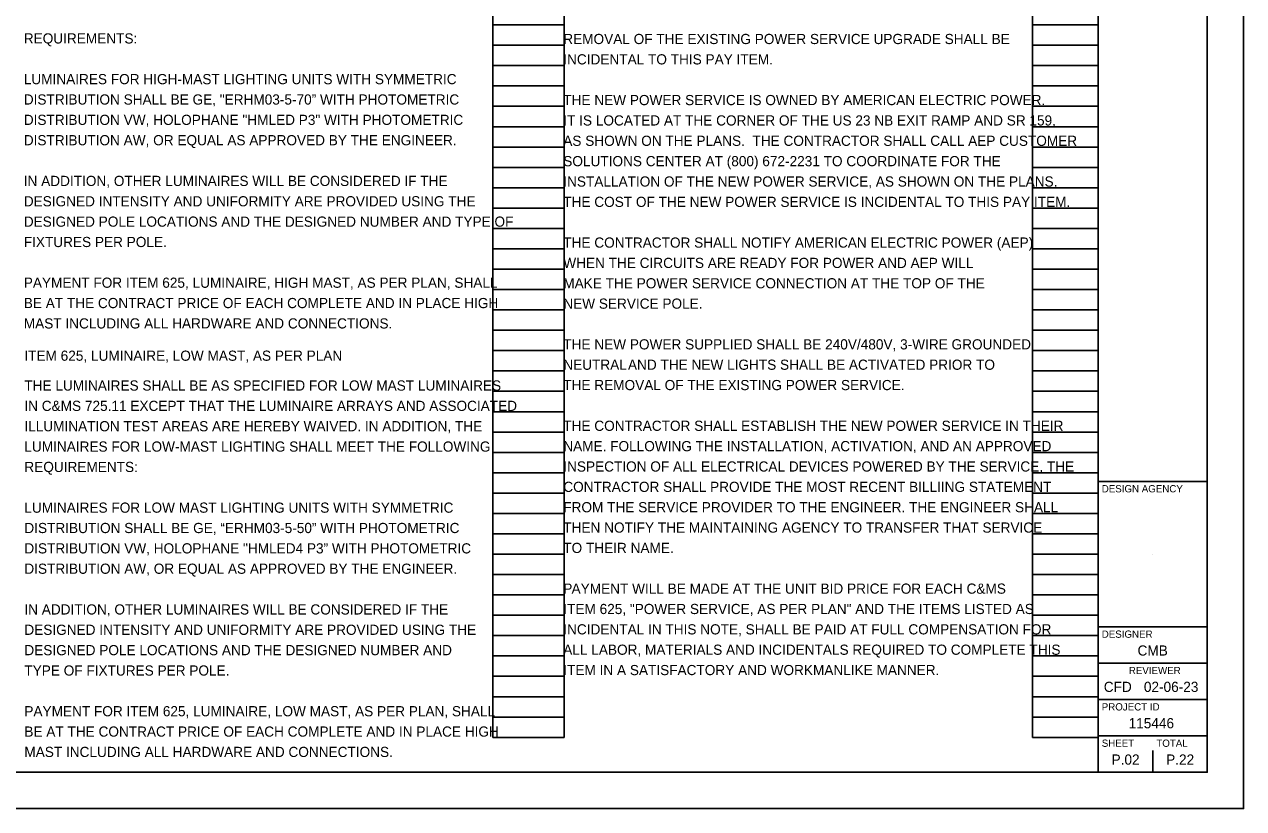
# Model space of a CAD drawing. Extents: x 0 to 34, y 0 to 22.
# Drawn here: x 17.24 to 34, y 0 to 10.79 of the extents above; entities that cross this region are included whole.
import ezdxf

# ---------------------------------------------------------------- set-up
doc = ezdxf.new("R2010")
doc.units = 0
for name, color, linetype in [('Default', 7, 'Continuous'), ('SH_Border', 7, 'Continuous'), ('SH_Cut_Line', 7, 'Continuous'), ('SH_Data', 7, 'Continuous'), ('SH_Text', 7, 'Continuous')]:
    doc.layers.add(name, color=color, linetype=linetype)

msp = doc.modelspace()

# ---------------------------------------------------------------- linework, layer by layer
at = {"layer": 'SH_Border'}
for p, q in [((32, 0.5), (32, 21.5)), ((32, 4.5), (33.5, 4.5)), ((32, 2.5), (33.5, 2.5)), ((32, 2), (33.5, 2)), ((32, 1.5), (33.5, 1.5)), ((32, 1), (33.5, 1))]:
    msp.add_line(p, q, dxfattribs=at)
msp.add_lwpolyline([(1.5, 21.5), (33.5, 21.5), (33.5, 0.5), (1.5, 0.5)], close=True, dxfattribs=at)
at = {"layer": 'SH_Cut_Line'}
msp.add_lwpolyline([(0, 0), (34, 0), (34, 22), (0, 22)], close=True, dxfattribs=at)
at = {"layer": 'SH_Data'}
for p, q in [((23.68, 0.98), (23.68, 21.14)), ((24.66, 0.98), (24.66, 21.14)), ((31.1, 0.98), (31.1, 21.14)), ((32, 0.98), (32, 21.14)), ((23.68, 10.78), (24.66, 10.78)), ((31.1, 10.78), (32, 10.78)), ((23.68, 10.5), (24.66, 10.5)), ((31.1, 10.5), (32, 10.5)), ((23.68, 10.22), (24.66, 10.22)), ((31.1, 10.22), (32, 10.22)), ((23.68, 9.94), (24.66, 9.94)), ((31.1, 9.94), (32, 9.94)), ((23.68, 9.66), (24.66, 9.66)), ((31.1, 9.66), (32, 9.66)), ((23.68, 9.38), (24.66, 9.38)), ((31.1, 9.38), (32, 9.38)), ((23.68, 9.1), (24.66, 9.1)), ((31.1, 9.1), (32, 9.1)), ((23.68, 8.82), (24.66, 8.82)), ((31.1, 8.82), (32, 8.82)), ((23.68, 8.54), (24.66, 8.54)), ((31.1, 8.54), (32, 8.54)), ((23.68, 8.26), (24.66, 8.26)), ((31.1, 8.26), (32, 8.26)), ((23.68, 7.98), (24.66, 7.98)), ((31.1, 7.98), (32, 7.98)), ((23.68, 7.7), (24.66, 7.7)), ((31.1, 7.7), (32, 7.7)), ((23.68, 7.42), (24.66, 7.42)), ((31.1, 7.42), (32, 7.42)), ((23.68, 7.14), (24.66, 7.14)), ((31.1, 7.14), (32, 7.14)), ((23.68, 6.86), (24.66, 6.86)), ((31.1, 6.86), (32, 6.86)), ((23.68, 6.58), (24.66, 6.58)), ((31.1, 6.58), (32, 6.58)), ((23.68, 6.3), (24.66, 6.3)), ((31.1, 6.3), (32, 6.3)), ((23.68, 6.02), (24.66, 6.02)), ((31.1, 6.02), (32, 6.02)), ((23.68, 5.74), (24.66, 5.74)), ((31.1, 5.74), (32, 5.74)), ((23.68, 5.46), (24.66, 5.46)), ((31.1, 5.46), (32, 5.46)), ((23.68, 5.18), (24.66, 5.18)), ((31.1, 5.18), (32, 5.18)), ((23.68, 4.9), (24.66, 4.9)), ((31.1, 4.9), (32, 4.9)), ((23.68, 4.62), (24.66, 4.62)), ((31.1, 4.62), (32, 4.62)), ((23.68, 4.34), (24.66, 4.34)), ((31.1, 4.34), (32, 4.34)), ((23.68, 4.06), (24.66, 4.06)), ((31.1, 4.06), (32, 4.06)), ((23.68, 3.78), (24.66, 3.78)), ((31.1, 3.78), (32, 3.78)), ((23.68, 3.5), (24.66, 3.5)), ((31.1, 3.5), (32, 3.5)), ((32.75, 3.5), (32.75, 3.5)), ((23.68, 3.22), (24.66, 3.22)), ((31.1, 3.22), (32, 3.22)), ((23.68, 2.94), (24.66, 2.94)), ((31.1, 2.94), (32, 2.94)), ((23.68, 2.66), (24.66, 2.66)), ((31.1, 2.66), (32, 2.66)), ((23.68, 2.38), (24.66, 2.38)), ((31.1, 2.38), (32, 2.38)), ((23.68, 2.1), (24.66, 2.1)), ((31.1, 2.1), (32, 2.1)), ((23.68, 1.82), (24.66, 1.82)), ((31.1, 1.82), (32, 1.82)), ((23.68, 1.54), (24.66, 1.54)), ((31.1, 1.54), (32, 1.54)), ((23.68, 1.26), (24.66, 1.26)), ((31.1, 1.26), (32, 1.26)), ((23.68, 0.98), (24.66, 0.98)), ((31.1, 0.98), (32, 0.98)), ((32.375, 0.675), (32.375, 0.675)), ((32.75, 0.5), (32.75, 0.8))]:
    msp.add_line(p, q, dxfattribs=at)

# ---------------------------------------------------------------- texts
at = {"layer": 'Default'}
for s, p in [('REQUIREMENTS: ', (17.232, 10.524)), ('LUMINAIRES FOR HIGH-MAST LIGHTING UNITS WITH SYMMETRIC ', (17.232, 9.964)), ('DISTRIBUTION SHALL BE GE, "ERHM03-5-70” WITH PHOTOMETRIC ', (17.232, 9.684)), ('DISTRIBUTION VW, HOLOPHANE "HMLED P3" WITH PHOTOMETRIC ', (17.232, 9.404)), ('DISTRIBUTION AW, OR EQUAL AS APPROVED BY THE ENGINEER.  ', (17.232, 9.124)), ('IN ADDITION, OTHER LUMINAIRES WILL BE CONSIDERED IF THE ', (17.232, 8.564)), ('DESIGNED INTENSITY AND UNIFORMITY ARE PROVIDED USING THE ', (17.232, 8.284)), ('DESIGNED POLE LOCATIONS AND THE DESIGNED NUMBER AND TYPE OF ', (17.232, 8.004)), ('FIXTURES PER POLE.', (17.232, 7.724)), ('PAYMENT FOR ITEM 625, LUMINAIRE, HIGH MAST, AS PER PLAN, SHALL ', (17.232, 7.164)), ('BE AT THE CONTRACT PRICE OF EACH COMPLETE AND IN PLACE HIGH ', (17.232, 6.884)), ('MAST INCLUDING ALL HARDWARE AND CONNECTIONS.', (17.232, 6.604)), ('ITEM 625, LUMINAIRE, LOW MAST, AS PER PLAN', (17.24, 6.16)), ('THE LUMINAIRES SHALL BE AS SPECIFIED FOR LOW MAST LUMINAIRES ', (17.24, 5.75)), ('IN C&MS 725.11 EXCEPT THAT THE LUMINAIRE ARRAYS AND ASSOCIATED ', (17.24, 5.47)), ('ILLUMINATION TEST AREAS ARE HEREBY WAIVED. IN ADDITION, THE ', (17.24, 5.19)), ('LUMINAIRES FOR LOW-MAST LIGHTING SHALL MEET THE FOLLOWING ', (17.24, 4.91)), ('REQUIREMENTS: ', (17.24, 4.63)), ('LUMINAIRES FOR LOW MAST LIGHTING UNITS WITH SYMMETRIC ', (17.24, 4.07)), ('DISTRIBUTION SHALL BE GE, “ERHM03-5-50” WITH PHOTOMETRIC ', (17.24, 3.79)), ('DISTRIBUTION VW, HOLOPHANE "HMLED4 P3” WITH PHOTOMETRIC ', (17.24, 3.51)), ('DISTRIBUTION AW, OR EQUAL AS APPROVED BY THE ENGINEER. ', (17.24, 3.23)), ('IN ADDITION, OTHER LUMINAIRES WILL BE CONSIDERED IF THE ', (17.24, 2.67)), ('DESIGNED INTENSITY AND UNIFORMITY ARE PROVIDED USING THE ', (17.24, 2.39)), ('DESIGNED POLE LOCATIONS AND THE DESIGNED NUMBER AND ', (17.24, 2.11)), ('TYPE OF FIXTURES PER POLE.', (17.24, 1.83)), ('PAYMENT FOR ITEM 625, LUMINAIRE, LOW MAST, AS PER PLAN, SHALL ', (17.24, 1.27)), ('BE AT THE CONTRACT PRICE OF EACH COMPLETE AND IN PLACE HIGH ', (17.24, 0.99)), ('MAST INCLUDING ALL HARDWARE AND CONNECTIONS.', (17.24, 0.71))]:
    msp.add_text(s, height=0.14, dxfattribs=at).set_placement(p)
at = {"layer": 'SH_Data'}
for s, height, p in [('DESIGN AGENCY', 0.1, (32.05, 4.35)), ('DESIGNER', 0.1, (32.05, 2.35)), ('CMB', 0.14, (32.542, 2.105)), ('REVIEWER', 0.1, (32.422, 1.85)), ('CFD', 0.14, (32.078, 1.605)), ('02-06-23', 0.14, (32.629, 1.605)), ('PROJECT ID', 0.1, (32.05, 1.35)), ('115446', 0.14, (32.419, 1.105)), ('SHEET', 0.1, (32.05, 0.85)), ('TOTAL', 0.1, (32.8, 0.85)), ('P.02', 0.14, (32.185, 0.605)), ('P.22', 0.14, (32.935, 0.605))]:
    msp.add_text(s, height=height, dxfattribs=at).set_placement(p)
at = {"layer": 'SH_Text'}
for s, p in [('REMOVAL OF THE EXISTING POWER SERVICE UPGRADE SHALL BE ', (24.648, 10.516)), ('INCIDENTAL TO THIS PAY ITEM.', (24.648, 10.236)), ('THE NEW POWER SERVICE IS OWNED BY AMERICAN ELECTRIC POWER.', (24.648, 9.676)), ('IT IS LOCATED AT THE CORNER OF THE US 23 NB EXIT RAMP AND SR 159,', (24.648, 9.396)), ('AS SHOWN ON THE PLANS.  THE CONTRACTOR SHALL CALL AEP CUSTOMER', (24.648, 9.116)), ('SOLUTIONS CENTER AT (800) 672-2231 TO COORDINATE FOR THE ', (24.648, 8.836)), ('INSTALLATION OF THE NEW POWER SERVICE, AS SHOWN ON THE PLANS.  ', (24.648, 8.556)), ('THE COST OF THE NEW POWER SERVICE IS INCIDENTAL TO THIS PAY ITEM.', (24.648, 8.276)), ('THE CONTRACTOR SHALL NOTIFY AMERICAN ELECTRIC POWER (AEP)', (24.648, 7.716)), ('WHEN THE CIRCUITS ARE READY FOR POWER AND AEP WILL', (24.648, 7.436)), ('MAKE THE POWER SERVICE CONNECTION AT THE TOP OF THE ', (24.648, 7.156)), ('NEW SERVICE POLE.', (24.648, 6.876)), ('THE NEW POWER SUPPLIED SHALL BE 240V/480V, 3-WIRE GROUNDED ', (24.648, 6.316)), ('NEUTRAL ', (24.648, 6.036)), ('AND THE NEW LIGHTS SHALL BE ACTIVATED PRIOR TO ', (25.537, 6.036)), ('THE REMOVAL OF THE EXISTING POWER SERVICE. ', (24.648, 5.756)), ('THE CONTRACTOR SHALL ESTABLISH THE NEW POWER SERVICE IN THEIR ', (24.648, 5.196)), ('NAME. FOLLOWING THE INSTALLATION, ACTIVATION, AND AN APPROVED ', (24.648, 4.916)), ('INSPECTION OF ALL ELECTRICAL DEVICES POWERED BY THE SERVICE, THE ', (24.648, 4.636)), ('CONTRACTOR SHALL PROVIDE THE MOST RECENT BILLIING STATEMENT ', (24.648, 4.356)), ('FROM THE SERVICE PROVIDER TO THE ENGINEER. THE ENGINEER SHALL ', (24.648, 4.076)), ('THEN NOTIFY THE MAINTAINING AGENCY TO TRANSFER THAT SERVICE ', (24.648, 3.796)), ('TO THEIR NAME.', (24.648, 3.516)), ('P', (24.648, 2.956)), ('AYMENT WILL BE MADE AT THE UNIT BID PRICE FOR EACH C&MS', (24.762, 2.956)), ('ITEM 625, "POWER SERVICE, AS PER PLAN" AND THE ITEMS LISTED AS ', (24.648, 2.676)), ('INCIDENTAL IN THIS NOTE, SHALL BE PAID AT FULL COMPENSATION FOR ', (24.648, 2.396)), ('ALL LABOR, MATERIALS AND INCIDENTALS REQUIRED TO COMPLETE THIS ', (24.648, 2.116)), ('ITEM IN A SATISFACTORY AND WORKMANLIKE MANNER.', (24.648, 1.836))]:
    msp.add_text(s, height=0.14, dxfattribs=at).set_placement(p)

doc.saveas('drawing.dxf')
